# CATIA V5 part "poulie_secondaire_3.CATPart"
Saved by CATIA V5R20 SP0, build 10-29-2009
Part number: poulie_secondaire_3
Bounding box of the stored display mesh (mm): x 605.778 to 685.778, y 1040.996 to 1480.934, z -671.801 to -231.946
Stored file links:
  C:\Users\Mike-7\Desktop\MMS_GR3\bfoltzer\CFAO_bfoltzer\poulie_secondaire_3.CATPart
  D:\ecole\thinkmotion\Eolienne.CATProduct
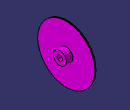
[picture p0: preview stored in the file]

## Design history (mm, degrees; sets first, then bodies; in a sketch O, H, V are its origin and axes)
Set1
  Plane1: linked copy from another document
  Point1 to Point6: linked copy from another document
  Line1: linked copy from another document
  Point7: linked copy from another document
  Point8: linked copy from another document
Body1 (main body)
  Sketch1 on Plane1, origin (0, -4693.0166, -1634.1991), H (1, 0, 0), V (0, -0.9808, -0.1948)
    point P1 (605.7782, -6035.2385)
    line L1 (605.7782, -6035.2385) -> (625.7782, -6035.2385)
    line L2 (625.7782, -6035.2385) -> (625.7782, -6015.2385)
    line L3 (625.7782, -6015.2385) -> (605.7782, -6015.2385)
    line L4 (605.7782, -6015.2385) -> (605.7782, -6035.2385)
    point P3 (625.7782, -6015.2385)
    reference projected point E1 (625.7782, -6015.2385) from Point1
    reference projected point E2 (605.7782, -6035.2385) from Point2
    point P5 (625.7782, -6050.2385)
    line L5 (625.7782, -6050.2385) -> (635.7782, -6050.2385)
    line L6 (635.7782, -6050.2385) -> (635.7782, -5850.2385)
    line L7 (635.7782, -5850.2385) -> (625.7782, -5850.2385)
    line L8 (625.7782, -5850.2385) -> (625.7782, -6050.2385)
    point P6 (635.7782, -6050.2385)
    point P7 (635.7782, -5850.2385)
    reference projected point E3 (635.7782, -5850.2385) from Point3
    reference projected point E4 (625.7782, -6050.2385) from Point4
    line L9 (685.7782, -6050.2385) -> (635.7782, -6050.2385)
    line L10 (635.7782, -6050.2385) -> (635.7782, -6020.2385)
    line L11 (635.7782, -6020.2385) -> (685.7782, -6020.2385)
    line L12 (685.7782, -6020.2385) -> (685.7782, -6050.2385)
    point P10 (635.7782, -6050.2385)
    point P12 (685.7782, -6020.2385)
    reference projected point E5 (685.7782, -6020.2385) from Point5
    reference projected point E6 (635.7782, -6050.2385) from Point6
    horizontal: L1 H, L3 H, L5 H, L7 H, L9 H, L11 H
    vertical: L2 V, L4 V, L6 V, L8 V, L10 V, L12 V
    coincidence: P3 E1, P1 E2, P7 E3, P5 E4, P12 E5, P10 E6, P6 P10
  Shaft1: profile Sketch1, axis Line1, angle 360
  Sketch2 on Plane1, origin (0, -4693.0166, -1634.1991), H (1, 0, 0), V (0, -0.9808, -0.1948)
    point P1 (629.2782, -5851.2385)
    line L1 (629.2782, -5851.2385) -> (632.2782, -5851.2385)
    line L2 (632.2782, -5851.2385) -> (632.2782, -5850.2385)
    line L3 (632.2782, -5850.2385) -> (629.2782, -5850.2385)
    line L4 (629.2782, -5850.2385) -> (629.2782, -5851.2385)
    point P3 (632.2782, -5850.2385)
    reference projected point E1 (629.2782, -5851.2385) from Point7
    reference projected point E2 (632.2782, -5850.2385) from Point8
    horizontal: L1 H, L3 H
    vertical: L2 V, L4 V
    coincidence: P1 E1, P3 E2
  Groove1: profile Sketch2, axis Line1, angle 360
